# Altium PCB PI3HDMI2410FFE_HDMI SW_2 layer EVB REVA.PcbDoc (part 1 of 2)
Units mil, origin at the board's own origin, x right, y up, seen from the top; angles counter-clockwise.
Board outline 4919 x 3441 mil, 2 copper layers (Top Layer, Bottom Layer); 75 components, 82 nets, 1371 pads, 135 vias.
Unrouted connection lines stored in the file: 1.
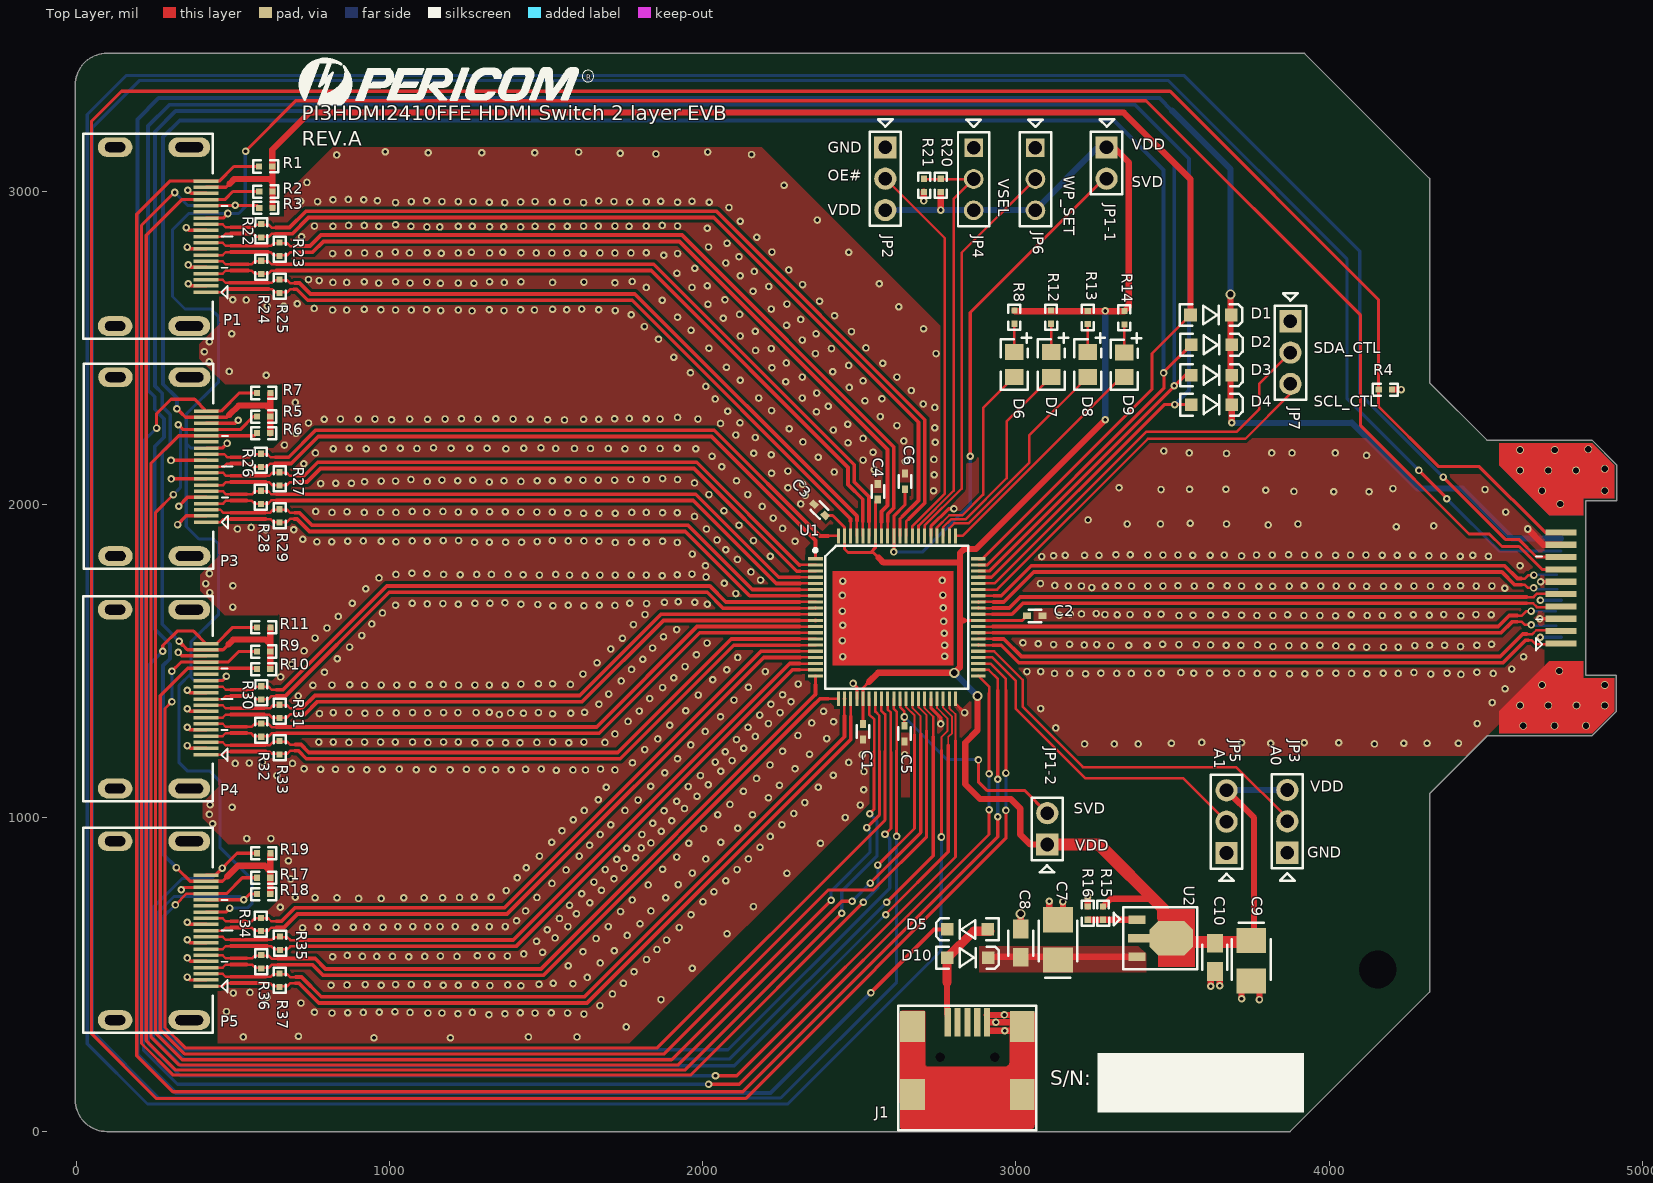
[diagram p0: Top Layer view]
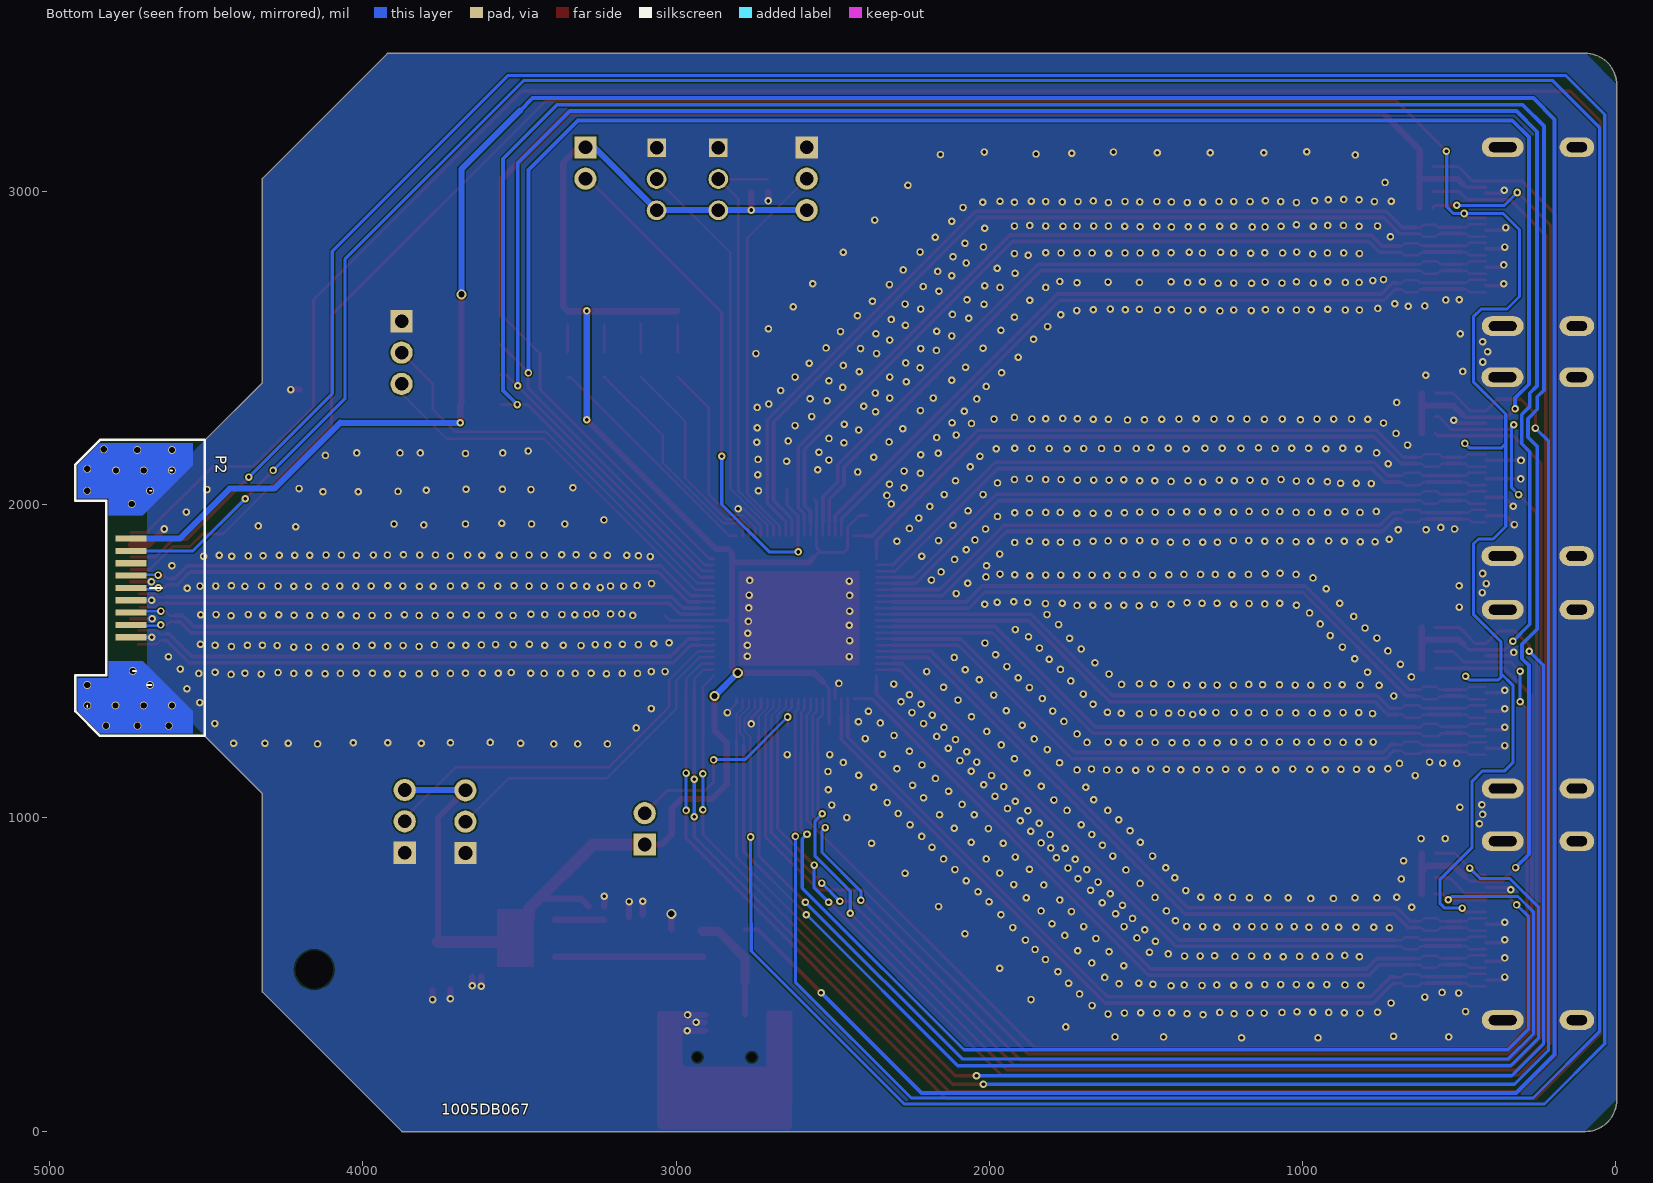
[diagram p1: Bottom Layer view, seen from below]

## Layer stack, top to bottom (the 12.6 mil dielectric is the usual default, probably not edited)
Top Layer: signal copper 1.4
Dielectric: core 12.6, FR-4, Dk 4.8
Bottom Layer: signal copper 1.4

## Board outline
-2,99 ccw(c98,99) 98,-1 3875,-1 4320,444 4320,1077 4505,1262 4838,1262 4916,1340 4916,1456 4819,1456 4819,2012 4917,2012 4917,2127 4838,2206 4503,2206 4320,2389 4320,3041 3921,3440 98,3440 ccw(c97.5,3340.5) -2,3340

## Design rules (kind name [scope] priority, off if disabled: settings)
Clearance [All] p1: gap=5
ComponentClearance [All] p1: gap=0 collisioncheckmode=3 verticalgap=0
DiffPairsRouting [All] p1: maxlimit=10 minlimit=8 mostfreqgap=10 toplayer_maxgap=8 toplayer_prefgap=8 bottomlayer_maxgap=8 bottomlayer_prefgap=8 maxuncoupledlength=500
HoleSize [All] p1: absolutevalues=TRUE maxlimit=500 minlimit=1 maxpercent=80.000 minpercent=20.000
PlaneConnect [All] p1: planeconnectstyle=Direct reliefexpansion=20 reliefentries=4 reliefconductorwidth=10 reliefairgap=10
PolygonConnect [All] p1: connectstyle=Direct reliefconductorwidth=10 reliefentries=4 polygonreliefangle="90 Angle"
RoomDefinition "PI3HDMI2410 demo board" [InComponentClass('PI3HDMI2410 demo board')] p1: confinementstyle=ConfineIn formatcopy=TRUE lockcomponents=FALSE outline -1506,-1019 22894,-1019 22894,6811 -1506,6811
RoutingVias [All] p1: holewidth=28 width=50 viastyle="Through Hole" minholewidth=8 minwidth=10 maxholewidth=28 maxwidth=50
SolderMaskExpansion [All] p1: expansion=4
TestPointUsage [All] p1: valid=0 allowmultiple=FALSE
Testpoint [All] p1: side=15 testpointundercomponent=TRUE minsize=40 maxsize=100 preferedsize=60 minholesize=0 maxholesize=40 preferedholesize=32 testpointgrid=1 style=1023 order=0123456789
Width [All] p1: maxlimit=100 minlimit=6 preferedwidth=10
15 further rules are at their usual default settings.

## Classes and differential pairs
differential pair NewDifferentialPair1: +D0+ -D0-
differential pair NewDifferentialPair2: +D0A+ -D0A-
differential pair NewDifferentialPair3: +D0B+ -D0B-
differential pair NewDifferentialPair4: +D0C+ -D0C-
differential pair NewDifferentialPair5: +D0D+ -D0D-
differential pair NewDifferentialPair6: +D1+ -D1-
differential pair NewDifferentialPair7: +D1A+ -D1A-
differential pair NewDifferentialPair8: +D1B+ -D1B-
differential pair NewDifferentialPair9: +D1C+ -D1C-
differential pair NewDifferentialPair10: +D1D+ -D1D-
differential pair NewDifferentialPair11: +D2+ -D2-
differential pair NewDifferentialPair12: +D2A+ -D2A-
differential pair NewDifferentialPair13: +D2B+ -D2B-
differential pair NewDifferentialPair14: +D2C+ -D2C-
differential pair NewDifferentialPair15: +D2D+ -D2D-
differential pair NewDifferentialPair16: +D3+ -D3-
differential pair NewDifferentialPair17: +D3A+ -D3A-
differential pair NewDifferentialPair18: +D3B+ -D3B-
differential pair NewDifferentialPair19: +D3C+ -D3C-
differential pair NewDifferentialPair20: +D3D+ -D3D-

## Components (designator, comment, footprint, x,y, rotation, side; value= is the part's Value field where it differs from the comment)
C1 "10n" CC_0402 2512,1275 r270 top
C2 "10n" CC_0402 3060,1645 r0 top
C3 "10n" CC_0402 2373,1983 r135 top
C4 "10n" CC_0402 2559,2041 r90 top
C5 "10n" CC_0402 2644,1269 r270 top
C6 "10n" CC_0402 2646,2074 r90 top
C7 "22u" CT_3528 3134,611 r90 top
C8 "1u" CC_0805 3015,600 r270 top
C9 "22u" CT_3528 3751,544 r270 top
C10 "1u" CC_0805 3635,555 r90 top
D1 "B0520LW" D_SOD_123 3622,2605 r0 top
D2 "B0520LW" D_SOD_123 3624,2510 r0 top
D3 "B0520LW" D_SOD_123 3624,2413 r0 top
D4 "B0520LW" D_SOD_123 3624,2319 r0 top
D5 "B0520LW" D_SOD_123 2845,644 r180 top
D6 "LED" LED_0805 2994,2447 r270 top
D7 "LED" LED_0805 3112,2447 r270 top
D8 "LED" LED_0805 3229,2447 r270 top
D9 "LED" LED_0805 3345,2446 r270 top
D10 "B0520LW" D_SOD_123 2846,554 r0 top
J1 "Mini USB 2.0 Type B Female" CON_USB2.0_MiniB_SMT 2845,29 r90 top
JP1-1 "CON 2" "2x1 Pin Header" 3289,3140 r270 top
JP1-2 "CON 2" "2x1 Pin Header" 3100,915 r90 top
JP2 "CON 3" "3x1 Pin Header" 2583,3140 r270 top
JP3 "CON 3" "3x1 Pin Header" 3866,889 r90 top
JP4 "CON 3" PLUG-3PIN@3PIN-100 2865,3139 r270 top
JP5 "CON 3" "3x1 Pin Header" 3672,888 r90 top
JP6 "CON 3" PLUG-3PIN@3PIN-100 3062,3139 r270 top
JP7 "CON 3" "3x1 Pin Header" 3876,2585 r270 top
P1 "HDMI-R" CON_HDMI_Recept 404,2678 r270 top
P2 "HDMI-T" CON_HDMI_Plug 4779,1734.05 r180 bottom
P3 "HDMI-R" CON_HDMI_Recept 405,1944 r270 top
P4 "HDMI-R" CON_HDMI_Recept 404,1202 r270 top
P5 "HDMI-R" CON_HDMI_Recept 404,463 r270 top
R1 "1K" R_0402 605,3079 r0 top
R2 "47K" R_0402 606,2999 r180 top
R3 "47K" R_0402 606,2947 r180 top
R4 "100k" R_0402 4179,2367 r180 top
R5 "47K" R_0402 599.05,2280.97 r180 top
R6 "47K" R_0402 599.05,2227.97 r180 top
R7 "1K" R_0402 599.05,2355.97 r0 top
R8 "1K" R_0402 2995,2598 r90 top
R9 "47K" R_0402 599.05,1530.97 r180 top
R10 "47K" R_0402 599.05,1474.97 r180 top
R11 "1K" R_0402 599.05,1607.97 r0 top
R12 "1K" R_0402 3112,2598 r90 top
R13 "1K" R_0402 3229,2597 r90 top
R14 "1K" R_0402 3346,2596 r90 top
R15 "NP" R_0402 3278,696 r90 top
R16 "0" R_0402 3229,696 r90 top
R17 "47K" R_0402 599.05,808.97 r180 top
R18 "47K" R_0402 599.05,756.97 r180 top
R19 "1K" R_0402 599.05,886.97 r0 top
R20 "1K" R_0402 2760,3019 r270 top
R21 "1K" R_0402 2707,3019 r270 top
R22 "620" R_0402 591,2874 r270 top
R23 "620" R_0402 650,2815 r270 top
R24 "620" R_0402 591,2757 r270 top
R25 "620" R_0402 650,2697 r270 top
R26 "620" R_0402 590,2141 r270 top
R27 "620" R_0402 650,2082 r270 top
R28 "620" R_0402 590,2023 r270 top
R29 "620" R_0402 650,1964 r270 top
R30 "620" R_0402 591,1399 r270 top
R31 "620" R_0402 650,1340 r270 top
R32 "620" R_0402 591,1280 r270 top
R33 "620" R_0402 650,1224 r270 top
R34 "620" R_0402 590,660 r270 top
R35 "620" R_0402 651,600 r270 top
R36 "620" R_0402 591,541 r270 top
R37 "620" R_0402 650,482 r270 top
U1 "PI3HDMI2410" LQFP80 2620,1640 r0 top
U2 "CJ1117-3.3" Pow_SOT_89 3441,616 r270 top
? "" "Lable Hole" 4155,516 r0 top
? "" PSC_LOG 820,3379 r0 top

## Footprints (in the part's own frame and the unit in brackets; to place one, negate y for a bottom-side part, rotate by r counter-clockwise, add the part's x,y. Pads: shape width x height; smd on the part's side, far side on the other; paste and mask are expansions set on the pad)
"2x1 Pin Header" [mm] "Pin Header 2x1 Pitch 2.54mm"
  rect 1.8x1.8 hole 1.1: 1(0,0)
  round 1.8 hole 1.1: 2(2.54,0)
  silkscreen extent -2.27,-1.27 3.81,1.27
"3x1 Pin Header" [mm] "Pin Header 3x1 Pitch 2.54mm"
  rect 1.8x1.8 / inner round 1.8 / far side rect 1.8x1.8 hole 1.1: 1(0,0)
  round 1.8 hole 1.1: 2(2.54,0) 3(5.08,0)
  silkscreen extent -2.27,-1.27 6.35,1.27
CC_0402 [mil]
  rect 25x20 smd: 1(-25,0) 2(25,0)
  silkscreen extent -20,-20 20,20
CC_0805 [mil]
  rect 60x50 smd: 1(-45,0) 2(45,0)
  silkscreen extent -40,-40 40,40
CON_HDMI_Plug [mm]
  rect 2.5x0.5 smd far side: 1(1,-4.5) 3(1,-3.5) 5(1,-2.5) 7(1,-1.5) 9(1,-0.5) 11(1,0.5) 13(1,1.5) 15(1,2.5) 17(1,3.5) 19(1,4.5)
  rect 2.5x0.5 smd: 2(1,-4) 4(1,-3) 6(1,-2) 8(1,-1) 10(1,0) 12(1,1) 14(1,2) 16(1,3) 18(1,4)
  round 0.635 hole 0.508: 20(-2.54,-9.525) 20(-2.54,-7.874) 20(-2.54,7.874) 20(-2.54,9.652) 20(-1.21,11.24) 20(-1.016,-11.176) 20(-0.254,-9.525) 20(-0.22,9.525) 20(1.067,6.807) 20(1.143,-6.731) 20(1.51,11.176) 20(1.524,-11.176) 20(2.032,-9.525) 20(2.032,9.525) 20(2.54,-7.874) 20(2.54,7.874) 20(4.064,-11.176) 20(4.318,-9.525) 20(4.318,9.525) 20(4.32,11.18)
  Top Layer region: -0.813,-5.944 1.968,-5.944 6.013,-9.989 6.013,-11.779 -1.517,-11.779 -1.524,-11.786 -3.302,-10.008 -3.302,-7.315 -0.813,-7.315
  Top Layer region: -0.813,5.893 1.968,5.893 6.013,9.938 6.013,11.728 -1.517,11.728 -1.524,11.735 -3.302,9.957 -3.302,7.264 -0.813,7.264
  Bottom Layer region: -0.813,-5.944 1.968,-5.944 6.013,-9.989 6.013,-11.779 -1.517,-11.779 -1.524,-11.786 -3.302,-10.008 -3.302,-7.315 -0.813,-7.315
  Bottom Layer region: -0.813,5.893 1.968,5.893 6.013,9.938 6.013,11.728 -1.517,11.728 -1.524,11.735 -3.302,9.957 -3.302,7.264 -0.813,7.264
  silkscreen extent -3.5,-12 7,12
CON_HDMI_Recept [mm]
  rect 0.28x2 smd: 1(0,0.281) 2(-0.5,0.281) 3(-1,0.281) 4(-1.5,0.281) 5(-2,0.281) 6(-2.5,0.281) 7(-3,0.281) 8(-3.5,0.281) 9(-4,0.281) 10(-4.5,0.281) 11(-5,0.281) 12(-5.5,0.281) 13(-6,0.281) 14(-6.5,0.281) 15(-7,0.281) 16(-7.5,0.281) 17(-8,0.281) 18(-8.5,0.281) 19(-9,0.281)
  oval 1.6x3.4 hole 0.8 slot 2.25 at 90 deg: 20(-11.75,-1.08) 21(2.75,-1.08)
  oval 1.6x2.8 hole 0.8 slot 1.65 at 90 deg: 22(-11.75,-7.09) 23(2.75,-7.09)
  silkscreen extent -12.82,-9.68 3.78,2.41
CON_USB2.0_MiniB_SMT [mm]
  rect 2.3x0.5 smd: 1(8.1,1.6) 2(8.1,0.8) 3(8.1,0) 4(8.1,-0.8) 5(8.1,-1.6)
  rect 2.5x2 smd: 5(2.25,4.45) 5(2.25,-4.45) 5(7.75,-4.45) 5(7.75,4.45)
  round 0 hole 0.762 unplated: 10(5.25,-2.2) 11(5.25,2.2)
  Top Layer region: 1.58,5.45 -0.35,5.45 -0.438,5.432 -0.513,5.383 -0.562,5.308 -0.58,5.22 -0.58,5.22 -0.58,-5.09 -0.553,-5.224 -0.477,-5.337 -0.364,-5.413 -0.23,-5.44 -0.23,-5.44 8.81,-5.44 8.875,-5.427 8.93,-5.39 8.967,-5.335 8.98,-5.27 8.98,-5.27 8.98,-3.59 8.968,-3.529 8.933,-3.477 8.881,-3.442 8.82,-3.43 8.82,-3.43 4.93,-3.43 4.758,-3.396 4.612,-3.298 4.514,-3.152 4.48,-2.98 4.48,-2.98 4.48,3.17 4.5,3.269 4.556,3.354 4.641,3.41 4.74,3.43 4.74,3.43 8.93,3.43 8.964,3.437 8.994,3.456 9.013,3.486 9.02,3.52 9.02,3.52 9.02,5.26 9.004,5.34 8.958,5.408 8.89,5.454 8.81,5.47 8.81,5.47 1.6,5.47 1.592,5.468 1.586,5.464 1.582,5.458 1.58,5.45
  silkscreen extent -0.65,-5.59 9.45,5.6
CT_3528 [mil]
  rect 80x95 smd: 1(-64,0) 2(64,0)
  silkscreen extent -121,-62 60,62
D_SOD_123 [mil]
  rect 40x40 smd: 1(-65,0) 2(65,0)
  silkscreen extent -100,-35 100,35
"Lable Hole" [mil]
  round 0 hole 120 unplated: ""(0,0)
LED_0805 [mm] "Chip Resistor; Body 2 x 1.3 mm (LxW typ)"
  rect 1.3x1.5 smd: 1(-1,0) 2(1,0)
  silkscreen extent -2.54,-1.09 2.03,1.4
LQFP80 [mm]
  rect 1.2x0.25 smd: 1(-6.6,4.75) 2(-6.6,4.25) 3(-6.6,3.75) 4(-6.6,3.25) 5(-6.6,2.75) 6(-6.6,2.25) 7(-6.6,1.75) 8(-6.6,1.25) 9(-6.6,0.75) 10(-6.6,0.25) 11(-6.6,-0.25) 12(-6.6,-0.75) 13(-6.6,-1.25) 14(-6.6,-1.75) 15(-6.6,-2.25) 16(-6.6,-2.75) 17(-6.6,-3.25) 18(-6.6,-3.75) 19(-6.6,-4.25) 20(-6.6,-4.75) 41(6.6,-4.75) 42(6.6,-4.25) 43(6.6,-3.75) 44(6.6,-3.25) 45(6.6,-2.75) 46(6.6,-2.25) 47(6.6,-1.75) 48(6.6,-1.25) 49(6.6,-0.75) 50(6.6,-0.25) 51(6.6,0.25) 52(6.6,0.75) 53(6.6,1.25) 54(6.6,1.75) 55(6.6,2.25) 56(6.6,2.75) 57(6.6,3.25) 58(6.6,3.75) 59(6.6,4.25) 60(6.6,4.75)
  rect 0.25x1.2 smd: 21(-4.75,-6.6) 22(-4.25,-6.6) 23(-3.75,-6.6) 24(-3.25,-6.6) 25(-2.75,-6.6) 26(-2.25,-6.6) 27(-1.75,-6.6) 28(-1.25,-6.6) 29(-0.75,-6.6) 30(-0.25,-6.6) 31(0.26,-6.6) 32(0.75,-6.6) 33(1.25,-6.6) 34(1.76,-6.6) 35(2.25,-6.6) 36(2.75,-6.6) 37(3.25,-6.6) 38(3.75,-6.6) 39(4.25,-6.6) 40(4.75,-6.6) 61(4.75,6.6) 62(4.25,6.6) 63(3.75,6.6) 64(3.24,6.6) 65(2.75,6.6) 66(2.25,6.6) 67(1.75,6.6) 68(1.25,6.6) 69(0.75,6.6) 70(0.25,6.6) 71(-0.25,6.6) 72(-0.75,6.6) 73(-1.25,6.6) 74(-1.75,6.6) 75(-2.26,6.6) 76(-2.75,6.6) 77(-3.25,6.6) 78(-3.75,6.6) 79(-4.25,6.6) 80(-4.75,6.6)
  silkscreen extent -6.73,-5.79 5.79,5.79
PLUG-3PIN@3PIN-100 [mm] "Pin Header 3x1 Pitch 2.54mm"
  rect 1.5x1.5 hole 1.1: 1(0,0)
  round 1.6 hole 1.1: 2(2.54,0) 3(5.08,0)
  silkscreen extent -2.27,-1.27 6.35,1.27
Pow_SOT_89 [mm] "SOT-89; Body 4.6 x 4.25 mm, inc. leads (LxW max)"
  rect 0.7x1.35 smd: 1(-1.5,-1.388) 3(1.5,-1.388)
  oct 2.8x3.5 smd: 2(0,1.388)
  rect 0.7x1.9 smd: 2(0,-1.163)
  Top Layer region: -2.346,0.336 -2.346,3.302 2.322,3.302 2.323,3.303 2.323,0.338 2.325,0.336
  silkscreen extent -2.5,-3.28 2.5,3.49
PSC_LOG [mil]
  silkscreen extent -107,-103 833,45
R_0402 [mm]
  rect 0.5x0.5 smd: 1(-0.532,-0.001) 2(0.54,-0.001)
  silkscreen extent -1.02,-0.49 1.02,0.49

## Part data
C1 C2 C3 C4 C5 C6 C8 C10: library part "CAP NP"
C7 C9: library part CAP
D1 D2 D3 D4 D5 D10: library part "Diode B0520LW"
J1: library part "USB 2_0.0 Mini B Female"
P1 P2 P3 P4 P5: library part "CON HDMI19_A pin mame"
R1 R2 R3 R4 R5 R6 R7 R8 R9 R10 R11 R12 R13 R14 R15 R16 R17 R18 R19 R20 R21: library part R
R22 R23 R24 R25 R26 R27 R28 R29 R30 R31 R32 R33 R34 R35 R36 R37: library part R_0402
U2: library part Pow_LDO_3.3V

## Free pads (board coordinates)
  round 24 hole 12: 4(61020,24994) 6(1717,2967) 7(1720,2889) 9(1720,2708) 10(1721,2619) 11(1620,2964) 12(1620,2889) 13(1619,2802) 14(1621,2710) 15(1614,2624) 16(1520,2966) 17(1519,2887) 18(1519,2803) 19(1521,2709) 20(1521,2623) 21(1419,2966) 22(1419,2886) 23(1420,2804) 24(1420,2711) 25(1419,2622) 26(1319,2965) 27(1320,2887) 28(1320,2803) 29(1320,2711) 30(1319,2622) 31(1220,2621) 32(1220,2707) 33(1220,2803) 34(1220,2888) 35(1220,2967) 36(1119,2970) 37(1120,2886) 38(1121,2804) 39(1120,2710) 40(1119,2622) 41(1020,2621) 42(1020,2711) 43(1019,2806) 44(1020,2893) 45(920,2891) 46(921,2803) 47(920,2711) 48(920,2623) 49(543,2653) 50(820,2709) 51(819,2801) 52(820,2888) 53(1020,2964) 54(918,2973) 55(820,2973) 56(720,2855) 57(742,2718) 58(500,2654) 59(1820,2967) 60(1820,2889) 61(1820,2804) 62(1820,2693) 63(1814,2568) 64(1920,2965) 65(1920,2889) 66(1920,2801) 67(1920,2598) 68(2040,2337) 69(2021,2965) 70(2015,2882) 71(2015,2698) 72(2020,2499) 73(2080,2298) 74(2120,2904) 75(2116,2791) 76(2118,2607) 77(2120,2397) 78(2119,2261) 79(2221,2806) 80(2211,2696) 81(2220,2300) 82(2030,2154) 83(2061,2121) 84(2320,2200) 85(2318,2407) 86(2313,2591) 87(2319,2702) 88(2421,2603) 89(2411,2498) 90(2401,2314) 91(2420,2104) 92(2521,2500) 93(2512,2395) 94(2512,2211) 95(2620,2252) 96(2620,2407) 97(2737,2044) 98(2738,2144) 99(2741,2245) 100(2704,2321) 101(2318,2340) 102(2417,2238) 103(2512,2142) 104(2019,2822) 105(2120,2730) 106(2219,2624) 107(2318,2525) 108(2415,2424) 109(2518,2331) 110(1918,2738) 111(2017,2639) 112(2120,2538) 113(2219,2498) 114(2221,2437) 115(1920,2278) 116(1820,2274) 117(1719,2274) 118(1620,2272) 119(1450,2272) 120(1395,2273) 121(1283,2273) 122(844,2273) 123(792,2272) 124(742,2260) 125(665,2190) 126(702,2227) 127(3258,1553) 128(3242,1735) 129(3256,1652) 132(1420,2074) 133(1319,2072) 134(1218,2076) 135(1121,2074) 136(879,2068) 137(829,2068) 138(781,2067) 139(817,1975) 140(920,1975) 141(1021,1975) 142(1707,978) 144(727,2130) 145(764,2165) 146(981,2180) 147(1312,2180) 149(1429,2180) 150(2012,1922) 151(1351,1330) 152(1688,1241) 153(1804,904) 154(821,2178) 155(872,2180) 156(926,2178) 157(1035,2180) 158(1088,2179) 159(1141,2181) 160(1197,2180) 161(1372,2178) 162(1257,2180) 163(1484,2181) 164(1531,2179) 165(1591,2179) 166(1642,2179) 167(1699,2179) 168(1752,2178) 169(1809,2179) 170(1864,2179) 171(1978,2178) 172(1919,2180) 173(901,2273) 174(954,2273) 175(1340,2274) 176(1007,2271) 177(1065,2273) 178(1122,2272) 179(1178,2273) 180(1230,2274) 181(1505,2271) 182(1559,2270) 183(1668,2272) 184(1766,2275) 185(1864,2273) 186(1985,2273) 187(2057,2259) 188(869,2974) 189(962,2970) 190(1070,2967) 191(1168,2967) 192(1267,2967) 193(1368,2964) 194(1465,2967) 195(1567,2967) 196(1668,2969) 197(1767,2966) 198(1866,2968) 199(1966,2968) 200(1871,2891) 201(1765,2888) 202(1667,2889) 203(1568,2888) 204(1465,2888) 205(1365,2887) 206(1265,2888) 207(1161,2886) 208(1069,2888) 209(1064,2803) 210(1166,2802) 211(1262,2805) 212(1362,2805) 213(1469,2803) 214(1567,2803) 215(1672,2803) 216(1720,2803) 217(1771,2803) 218(1775,2712) 219(1772,2606) 220(1668,2622) 221(1566,2622) 222(1463,2621) 223(1366,2619) 224(1367,2709) 225(1270,2706) 226(1163,2706) 227(1066,2707) 228(966,2707) 229(968,2800) 230(966,2888) 231(870,2891) 232(869,2803) 233(864,2709) 234(864,2621) 235(819,2621) 236(760,2626) 237(706,2641) 238(771,2967) 239(717,2968) 240(761,2889) 241(776,2715) 242(1876,2796) 243(1871,2652) 244(1859,2528) 245(1975,2754) 246(1966,2693) 247(1963,2556) 248(2071,2654) 249(2066,2595) 250(2078,2834) 251(2074,2771) 252(2084,2948) 253(2173,2853) 254(2275,2749) 255(2373,2649) 256(2475,2552) 257(2575,2451) 258(2269,2640) 259(2268,2572) 260(2165,2744) 261(2161,2681) 262(2362,2545) 263(2360,2482) 264(2267,2452) 265(2265,2392) 266(2168,2553) 267(2169,2492) 268(2364,2356) 269(2363,2296) 270(2276,2242) 271(2179,2340) 272(2076,2438) 273(2463,2256) 274(2464,2197) 275(2369,2151) 276(2168,2214) 277(2219,2159) 278(2272,2107) 279(2319,2065) 280(2106,2222) 281(2163,2164) 282(2220,2100) 283(2272,2054) 284(2313,2002) 285(2466,2444) 286(2468,2374) 287(2572,2338) 288(2567,2281) 289(2666,2364) 290(2642,2203) 291(2742,2199) 292(2739,2095) 293(2544,2167) 294(973,2622) 295(1070,2621) 296(1164,2619) 297(1264,2618) 298(1908,2470) 299(1961,2421) 300(2010,2377) 301(921,2073) 302(974,2075) 303(1020,2075) 304(1069,2080) 305(1168,2078) 306(1266,2078) 307(1366,2076) 308(1472,2076) 309(1520,2076) 310(1571,2079) 311(1618,2078) 312(1667,2078) 313(1719,2078) 314(1771,2080) 315(1820,2080) 316(1872,2083) 317(1920,2080) 318(1974,2069) 319(2020,2032) 320(2068,1980) 321(2116,1934) 322(2162,1885) 323(2216,1835) 324(765,1978) 325(865,1977) 326(972,1975) 327(1073,1978) 328(1119,1976) 329(1171,1978) 330(1171,1978) 331(1220,1976) 332(1271,1977) 333(1320,1977) 334(1370,1977) 335(1420,1976) 336(1471,1976) 337(1520,1976) 338(1569,1974) 339(1620,1972) 340(1669,1972) 341(1721,1972) 342(1774,1975) 343(1820,1975) 344(1872,1974) 345(1919,1974) 346(1974,1962) 347(2046,1887) 348(2074,1856) 349(2111,1825) 350(2154,1785) 351(2185,1759) 352(515,1922) 353(559,1927) 354(606,1920) 355(695,1920) 356(724,1889) 357(769,1881) 358(867,1883) 359(917,1884) 360(974,1883) 361(1021,1881) 362(1073,1884) 363(1121,1883) 364(1172,1885) 365(1221,1885) 366(1272,1880) 367(1319,1880) 368(1371,1880) 369(1422,1880) 370(1472,1882) 371(1520,1885) 372(1571,1884) 373(1621,1884) 374(1669,1883) 375(1721,1879) 376(1773,1880) 377(1820,1880) 378(1872,1883) 379(1919,1879) 380(1967,1842) 381(2009,1805) 382(2069,1749) 383(2106,1716) 384(1021,1777) 385(1120,1779) 386(1072,1781) 387(1173,1777) 388(1226,1776) 389(1279,1777) 390(1326,1777) 391(1379,1777) 392(1427,1776) 393(1479,1775) 394(1531,1777) 395(1575,1775) 396(1625,1774) 397(1672,1775) 398(1721,1775) 399(1772,1775) 400(1820,1775) 401(1871,1773) 402(1919,1776) 403(1966,1778) 404(2011,1769) 405(1020,1679) 406(967,1766) 407(925,1731) 408(882,1685) 409(837,1643) 410(801,1606) 411(763,1574) 412(728,1533) 413(688,1490) 414(653,1450) 415(709,1389) 416(756,1423) 417(793,1465) 418(834,1508) 419(873,1545) 420(912,1582) 421(944,1619) 422(978,1654) 423(1073,1685) 424(1121,1683) 425(1171,1684) 426(1220,1682) 427(1273,1685) 428(1321,1685) 429(1369,1687) 430(1420,1682) 431(1474,1681) 432(1522,1677) 433(1571,1679) 434(1621,1677) 435(1670,1679) 436(1720,1678) 437(1767,1685) 438(1821,1684) 439(1878,1688) 440(1922,1690) 441(1975,1688) 442(2015,1682) 443(817,1424) 444(874,1425) 445(921,1424) 446(974,1424) 447(1024,1424) 448(1074,1425) 449(1128,1425) 450(1172,1426) 451(1221,1424) 452(1273,1424) 453(1319,1424) 454(1370,1424) 455(1420,1427) 456(1476,1428) 457(1521,1428) 458(1578,1426) 459(1618,1459) 460(1663,1495) 461(1707,1539) 462(1744,1573) 463(1779,1617) 464(1816,1649) 465(777,1333) 466(821,1336) 467(871,1336) 468(922,1334) 469(969,1335) 470(1022,1335) 471(1074,1336) 472(1122,1335) 473(1173,1336) 474(1219,1336) 475(1277,1336) 476(1319,1337) 477(1387,1335) 478(1428,1334) 479(1476,1336) 480(1521,1332) 481(1579,1334) 482(1623,1337) 483(1669,1363) 484(1700,1395) 485(1740,1437) 486(1773,1474) 487(1809,1506) 488(1840,1542) 489(1875,1578) 490(1917,1601) 491(508,1174) 492(553,1175) 493(595,1178) 494(691,1174) 495(728,1157) 496(781,1155) 497(828,1155) 498(878,1155) 499(928,1154) 500(977,1155) 501(545,934) 501(622,934) 501(1032,1156) 501(1086,1154) 501(1139,1155) 501(1194,1154) 501(1885,610) 501(1925,650) 501(2087,1043) 501(2146,869) 501(2159,1010) 501(2183,906) 501(2326,1049) 501(2503,1041) 501(2514,1090) 501(2515,1148) 516(1389,1154) 550(1632,491) 566(1437,841) 571(641,1135) 577(678,863) 592(685,805) 593(652,715) 594(700,747) 595(763,745) 596(833,745) 597(902,743) 598(974,743) 599(1046,745) 600(1111,745) 601(1170,745) 602(1224,746) 603(1271,747) 604(1325,747) 605(1373,768) 606(1408,809) 607(1479,878) 608(1518,922) 610(1297,1154) 611(1246,1155) 612(1435,1155) 613(1339,1154) 614(1485,1156) 615(1533,1152) 616(1586,1153) 617(1626,1153) 618(1674,1156) 619(1720,1153) 620(1692,1098) 621(1667,1058) 622(1622,1024) 623(1587,994) 624(1551,959) 629(1776,1176) 630(1815,1218) 631(1857,1252) 632(1895,1296) 633(1946,1342) 634(1986,1392) 635(2032,1441) 636(2077,1473) 637(2112,1512) 638(723,649) 639(773,651) 640(830,651) 641(885,651) 642(928,652) 643(980,651) 644(1027,653) 645(1075,653) 646(1122,653) 647(1162,653) 648(1210,653) 649(1274,651) 650(1319,653) 651(1370,653) 652(1406,672) 653(1435,703) 654(1471,746) 655(1519,791) 656(1564,834) 657(1606,878) 658(1639,913) 659(1673,947) 660(1752,1024) 661(1794,1057) 662(1834,1101) 663(1879,1144) 664(1920,1189) 665(1962,1233) 666(2008,1276) 667(2057,1323) 668(2100,1376) 669(2146,1417) 670(2200,1467) 671(2305,1427) 672(2255,1393) 673(2282,1371) 674(2218,1363) 675(2182,1328) 676(2145,1289) 677(2108,1250) 678(2072,1211) 679(2040,1178) 680(1993,1135) 681(2247,1336) 682(2210,1301) 683(2168,1260) 684(2131,1222) 685(2094,1183) 686(2058,1149) 687(2018,1106) 688(1954,1100) 689(1982,1069) 690(1917,1053) 691(1942,1030) 692(1877,1023) 693(1901,991) 694(1841,983) 695(1868,957) 696(1806,947) 697(1835,920) 698(1758,903) 699(1786,873) 700(1726,868) 701(1749,840) 702(1689,835) 703(1653,795) 704(1614,758) 705(1575,721) 706(1543,679) 707(1504,643) 708(1470,606) 709(1429,566) 710(1717,806) 711(1677,769) 712(1640,729) 713(1597,694) 714(1570,653) 715(1529,617) 716(1489,571) 717(1377,559) 718(1327,559) 719(1281,560) 720(1216,558) 721(1163,559) 722(1113,558) 723(1062,557) 724(1010,558) 725(960,558) 726(914,558) 727(866,561) 728(819,557) 729(814,466) 730(865,467) 731(923,468) 732(974,466) 733(1020,468) 734(1070,468) 735(1121,468) 736(1172,466) 737(1220,466) 738(1274,467) 739(1321,465) 740(1378,467) 741(1420,464) 742(1478,469) 743(1523,472) 744(1571,528) 745(1618,573) 746(1660,615) 747(1699,653) 748(1738,701) 749(1775,738) 750(1826,786) 751(1872,836) 752(1917,875) 753(1956,919) 754(1586,471) 755(1673,537) 756(1718,576) 757(1759,625) 758(1800,662) 759(1835,703) 760(1882,745) 761(1922,787) 762(1967,824) 763(2003,966) 764(2048,1010) 765(2130,1085) 766(2172,1126) 767(2215,1169) 768(2255,1213) 769(2304,1263) 770(2010,869) 771(2058,922) 772(2112,967) 773(2210,1064) 774(2245,1104) 775(2295,1157) 776(2348,1303) 777(2386,1340) 778(2418,1307) 779(2396,1253) 780(2341,1203) 781(2466,1177) 782(2417,1136) 783(2369,1098) 784(2291,1014) 785(2253,978) 786(2216,941) 787(2110,835) 788(2074,799) 789(2036,764) 790(2001,732) 791(1963,691) 792(1854,580) 793(1821,548) 794(1781,509) 795(1747,472) 796(1712,438) 797(1672,401) 798(1621,374) 799(1569,377) 800(1517,378) 801(1465,377) 802(1418,378) 803(1369,375) 804(1318,372) 805(1265,379) 806(1219,375) 807(1168,377) 808(1123,377) 809(1066,379) 810(1018,381) 811(968,380) 812(917,379) 813(867,378) 814(817,377) 815(761,380) 816(718,409) 817(610,428) 818(555,443) 819(502,441) 820(4609,1805) 823(4508,1835) 824(4458,1838) 825(4418,1835) 826(4365,1836) 827(4318,1837) 828(4266,1838) 829(4217,1838) 830(4169,1838) 831(4117,1839) 832(4068,1839) 833(4020,1838) 834(3966,1839) 835(3921,1839) 836(3870,1840) 837(3818,1839) 838(3768,1839) 839(3720,1836) 840(3665,1839) 841(3620,1838) 842(3564,1838) 843(3517,1839) 844(3469,1839) 845(3421,1839) 846(3365,1840) 847(3319,1840) 848(3319,1840) 849(3265,1838) 850(3219,1838) 851(3157,1838) 852(3120,1837) 853(3082,1834) 854(3078,1748) 856(3124,1742) 857(3167,1740) 858(3209,1740) 859(3285,1739) 860(3326,1741) 861(3369,1740) 862(3421,1740) 863(3469,1740) 864(3517,1741) 865(3569,1740) 866(3621,1741) 867(3674,1741) 868(3720,1740) 869(3775,1739) 870(3819,1739) 871(3872,1740) 872(3920,1741) 873(3973,1740) 874(4022,1740) 875(4073,1740) 876(4119,1739) 877(4173,1739) 878(4220,1739) 879(4270,1740) 880(4323,1740) 881(4376,1739) 882(4419,1741) 883(4469,1740) 884(4519,1740) 885(4560,1733) 886(4517,1648) 887(4468,1649) 888(4420,1645) 889(4365,1649) 890(4319,1647) 891(4268,1648) 892(4219,1647) 893(4169,1646) 894(4121,1646) 895(4070,1648) 896(4020,1645) 897(3970,1646) 898(3919,1646) 899(3867,1648) 900(3820,1646) 901(3769,1646) 902(3720,1647) 903(3669,1648) 904(3621,1647) 905(3565,1647) 906(3520,1646) 907(3463,1650) 908(3419,1649) 909(3364,1649) 910(3323,1648) 911(3284,1649) 912(3209,1651) 913(3173,1651) 914(3022,1559) 915(3071,1556) 916(3120,1553) 917(3171,1554) 918(3218,1552) 919(3303,1550) 920(3360,1551) 921(3419,1551) 922(3468,1554) 923(3520,1553) 924(3576,1553) 925(3621,1552) 926(3671,1551) 927(3718,1551) 928(3771,1552) 929(3820,1547) 930(3871,1550) 931(3920,1549) 932(3970,1551) 933(4021,1549) 934(4072,1546) 935(4119,1545) 936(4173,1545) 937(4220,1545) 938(4273,1550) 939(4320,1551) 940(4368,1551) 941(4419,1547) 942(4471,1551) 943(4518,1554) 944(3035,1467) 945(3079,1467) 946(3123,1461) 947(3172,1461) 948(3222,1460) 949(3271,1462) 950(3322,1461) 951(3368,1461) 952(3421,1461) 953(3464,1462) 954(3526,1464) 955(3567,1462) 956(3618,1462) 957(3672,1462) 958(3720,1461) 959(3770,1461) 960(3820,1460) 961(3873,1460) 962(3922,1460) 963(3969,1462) 964(4021,1462) 965(4071,1461) 966(4120,1460) 967(4172,1462) 968(4220,1461) 969(4270,1464) 970(4324,1459) 971(4376,1462) 972(4420,1458) 973(4471,1465) 974(4523,1461) 975(4582,1475) 976(4620,1514) 977(775,1242) 978(821,1242) 979(871,1241) 980(921,1242) 981(972,1242) 982(1019,1242) 983(1074,1242) 984(1123,1241) 985(1173,1242) 986(1220,1242) 987(1273,1240) 988(1321,1240) 989(1371,1240) 990(1417,1240) 991(1471,1241) 992(1521,1242) 993(1573,1240) 994(1621,1242) 995(1720,1268) 996(1762,1308) 997(1798,1341) 998(1831,1381) 999(1872,1416) 1000(1908,1447) 1001(1944,1483) 1002(1980,1521) 1003(2014,1558) 1006(3230,1951) 1007(3329,2054) 1008(3672,2163) 1009(4119,2157) 1010(4203,2051) 1011(4333,1932) 1012(3881,2165) 1013(3472,2171) 1014(3355,1938) 1015(3463,2048) 1016(3670,2049) 1017(3887,2042) 1018(4127,2041) 1019(4019,2165) 1020(3816,2165) 1021(3553,2165) 1022(4014,2041) 1023(3797,2046) 1024(3554,2049) 1025(3556,1940) 1026(3461,1938) 1027(3672,1938) 1028(3805,1935) 1029(3900,1938) 1030(4497,2048) 1031(4563,1976) 1032(4214,1929) 1033(3079,1349) 1034(3127,1287) 1035(3219,1236) 1036(3314,1236) 1037(3390,1236) 1038(3496,1238) 1039(3593,1241) 1041(3720,1240) 1042(3813,1238) 1043(3920,1240) 1044(4030,1240) 1046(4144,1236) 1047(4238,1238) 1048(4312,1238) 1049(4412,1238) 1050(4472,1301) 1051(4520,1368) 1052(4561,1412) 1053(2108,2076) 1054(2144,2032) 1055(2190,1994) 1056(2225,1957) 1057(2255,1924) 1058(2295,1883) 1059(832,3116) 1060(737,3028) 1062(987,3126) 1063(1124,3123) 1065(1295,3123) 1066(1464,3123) 1069(1604,3125) 1070(1737,3121) 1072(1851,3119) 1074(2016,3125) 1076(2156,3117) 1079(2260,3019) 1082(2366,2908) 1085(2466,2805) 1088(2564,2705) 1090(2626,2631) 1092(2705,2561) 1094(2745,2482) 1097(2741,2310) 1098(534,301) 1099(480,382) 1101(710,303) 1104(951,298) 1107(1195,298) 1110(1444,301) 1112(1599,301) 1115(1756,333) 1117(1867,420) 1119(1967,520) 1121(2078,630) 1123(2162,717) 1125(2269,823) 1127(2376,919) 1129(2455,1001) 1131(700,2326) 1132(607,2413) 1133(489,2425) 1134(663,2633) 1135(610,2634) 1136(497,2545) 1137(816,1881)

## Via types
v1: diameter 24, hole 12, Top Layer to Bottom Layer, tented both sides, 131 vias
v2: diameter 32, hole 20, Top Layer to Bottom Layer, tented both sides, 4 vias

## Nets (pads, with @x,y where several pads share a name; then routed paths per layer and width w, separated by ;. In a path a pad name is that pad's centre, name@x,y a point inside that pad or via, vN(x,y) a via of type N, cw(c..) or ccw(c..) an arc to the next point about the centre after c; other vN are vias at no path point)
+5V: C7.1 C8.2 D10.2 U2.3 | length 472.4
  Top Layer w20: D10.2@2913.94,556.94 U2.3@3386.37,556.94
+5V_A: D1.1 P1.18 R1.2 R2.1 R3.1 U1.60 | length 4979.4
  Top Layer w10: P1.18@415.06,3012.65 478.65,3012.65 490,3024 ; U1.60@2879.84,1827.01 2893.01,1827.01 3434,2368 3434,2482 D1.1@3557,2605
  Top Layer w20: 490,3024 505,3039 618,3039 626.95,3030.05 ; R3.1@626.95,2947.03 626.95,3078.28 R1.2@626.27,3078.97 626.27,3132.27 745,3251 3344,3251 3557,3038 D1.1@3557,2605
+5V_B: D2.1 P3.18 R5.1 R6.1 R7.2 U1.59 | length 6271.7
  Top Layer w10: 339.11,2288.89 349.35,2278.65 481.65,2278.65 489,2286 ; U1.59@2879.84,1807.32 2908.32,1807.32 3472,2371 3472,2423 D2.1@3559,2510
  Top Layer w12: v1(322,2306) 339.11,2288.89
  Top Layer w20: 489,2286 519,2316 608,2316 620,2304 ; R6.1@620,2228 R7.2@620,2355.62
  Bottom Layer w12: v1(322,2306) 322,2340 278,2384 278,3173 331,3226 3313,3226 3471,3068 v1(3471,2420)
+5V_C: D3.1 P4.18 R9.1 R10.1 R11.2 U1.58 | length 7212
  Top Layer w10: 339.83,1552.17 355.35,1536.65 469.65,1536.65 487,1554 ; U1.58@2879.84,1787.64 2914.64,1787.64 3540,2413 D3.1@3559,2413
  Top Layer w12: v1@328.5,1563.5 339.83,1552.17
  Top Layer w20: 487,1554 502,1569 605,1569 620,1554 R10.1@620,1475 620.31,1475.31 R11.2@620.31,1607.94
  Bottom Layer w12: v1(329,1564) 275,1618 275,2168 301,2194 301,2287 275,2313 275,2355 252,2378 252,3190 318,3256 3339,3256 3505,3090 v1(3505,2379)
+5V_D: D4.1 P5.18 R17.1 R18.1 R19.2 U1.57 | length 8054.7
  Top Layer w10: v1@326.5,835.5 364.35,797.65 467.65,797.65 483,813 ; U1.57@2879.84,1767.95 2921.95,1767.95 3473,2319 D4.1@3559,2319
  Top Layer w12: v1(320.46,841.54) v1@326.5,835.5
  Top Layer w20: 483,813 517,847 602,847 620,829 ; R18.1@620,757 R19.2@620,886.62
  Bottom Layer w12: v1(320.46,841.54) 278,884 278,1486 300,1508 300,1554 251,1603 251,2185 281,2215 281,2274 251,2304 251,2344 230,2365 230,3208 298,3276 3380,3276 3552,3104 3552,2364 v1(3507,2319)
+5V_E: D1.2 D2.2 D3.2 D4.2 D5.2 P2.18 | length 11460.7
  Top Layer w13: v1(2537,442) 2739,644 D5.2@2780,644
  Top Layer w20: v2@3685,2670 3685,2323 D4.2@3689,2319 v1(3689,2261)
  Bottom Layer w13: v1(2537,442) 2217,122 319,122 196,245 196,3229 264,3297 3458,3297 3498.23,3256.77 ; v2@3685,2670 v2(3685,2671)
  Bottom Layer w20: 3498.23,3256.77 3685,3070 v2(3685,2671) ; v1@3687,2260 4070,2260 ; 4072,2261 4282,2051 4424,2051 4583.46,1891.54 P2.18@4739.63,1891.54
+5V_USB: D5.1 D10.1 J1.1 | length 351.3
  Top Layer w20: J1.1@2780.01,372.9 2780.01,476
  Top Layer w30: 2780.01,476 2780.01,553.01 2865,638 D5.1@2916,638
A0: JP3.2 U1.45 | length 1267.2
  Top Layer w8: U1.45@2879.84,1531.73 2930.27,1531.73 3021,1441 3021,1355 3213.69,1162.31 3702.69,1162.31 3866,999 JP3.2@3866,989
A1: JP5.2 U1.44 | length 1061.4
  Top Layer w8: U1.44@2879.84,1512.05 2924.95,1512.05 2999,1438 2999,1349 3222,1126 3534,1126 JP5.2@3672,988
CEC: P1.13 P2.13 P3.13 P4.13 P5.13 | length 8748.7
  Top Layer w10: P5.13@415.06,699.22 478.22,699.22 v1(491,712) ; P4.13@415.06,1438.22 468.22,1438.22 v1(480,1452) ; P1.13@415.06,2914.22 470.22,2914.22 v1(485,2929) ; P3.13@416.06,2180.22 467.22,2180.22 v1(482,2195) ; v1(541,3128) 701,3289 3415,3289 4100,2604 4100,2252 4446,1906 4511,1906 4551,1866 4606,1866 4678.89,1793.11 P2.13@4739.63,1793.11
  Bottom Layer w10: 352,2195 367,2180 467,2180 v1(482,2195) ; 367,1461 329,1423 329,1176 355,1150 426,1150 459,1117 459,906 562,803 562,727 547,712 v1(491,712) ; v1(480,1452) 468,1440 376,1440 367,1449 367,1562 455,1650 455,1874 439,1890 392,1890 352,1930 352,2289 455,2392 455,2599 430,2624 348,2624 308,2664 308,2877 360,2929 519,2929 540,2950 540,3128 v1(541,3128)
D0+: P2.10 U1.53 | length 1910.7
  Top Layer w8: U1.53@2880,1689.06 2928,1689.06 ; 4614.42,1743.74 4624,1743.74 4633.69,1734.06 v1(4652,1734.06)
  Top Layer w12: U1.53@2879.84,1689.21 U1.53@2880,1689.21 ; 2928,1689.06 2961.06,1689.06 3057,1785 4550.72,1785 4591.98,1743.74 4614.42,1743.74
  Bottom Layer w8: v1(4652,1734.06) 4656.06,1730 P2.10@4728,1730
D0-: P2.12 U1.54 | length 1906.1
  Top Layer w8: U1.54@2879.84,1708.9 2929.61,1708.9 ; 4612.94,1763.74 4624,1763.74 4635.26,1775 v1(4653,1775)
  Top Layer w12: 2929.61,1709.06 2952.77,1709.06 3048.71,1805 4559,1805 4600.26,1763.74 4612.94,1763.74
  Bottom Layer w8: v1@4654.57,1776 P2.12@4726,1776
D0A+: P1.10 R22.2 U1.70 | length 2965.8
  Top Layer w8: P1.10@415.06,2855.17 468.32,2855.17 478,2864.85 495,2864.85 ; 555,2864.85 565.15,2864.85 575.68,2854.32 614.32,2854.32 624,2864 637,2864 ; U1.70@2629.84,1899.84 2629.84,1954.13 2637.32,1961.61
  Top Layer w12: 495,2864.85 555,2864.85 ; 637,2864 690,2864 742,2916 2035.72,2916 2689,2262.72 2689,2013.28 2637.32,1961.61
D0A-: P1.12 R22.1 U1.69 | length 2998.4
  Top Layer w8: P1.12@415.06,2894.54 468.32,2894.54 478,2884.85 495,2884.85 ; 555,2884.85 566.85,2884.85 575.68,2893.68 614.32,2893.68 624,2884 638,2884 ; U1.69@2649.53,1899.84 2649.53,1945.53 2657.47,1953.47
  Top Layer w12: 495,2884.85 555,2884.85 ; 638,2884 681.72,2884 733.72,2936 2044,2936 2709,2271 2709,2005 2657.47,1953.47
D0B+: P3.10 R26.2 U1.1 | length 2187.6
  Top Layer w8: P3.10@416.06,2121.17 472.17,2121.17 481.85,2130.85 495,2130.85 ; 540,2130.85 555.46,2130.85 565,2121.32 610.32,2121.32 620,2131 635,2131 ; U1.1@2360.16,1827.01 2360.16,1860
  Top Layer w12: 495,2130.85 540,2130.85 ; 635,2131 687,2131 773,2217 2028.72,2217 2360.09,1885.63 ; 2360.16,1860 2360.16,1885.7
D0B-: P3.12 R26.1 U1.80 | length 2204.4
  Top Layer w8: P3.12@416.06,2160.54 473.32,2160.54 483,2150.85 495,2150.85 ; 540,2150.85 553.85,2150.85 563.68,2160.68 611.32,2160.68 621,2151 636,2151 ; 2400,1899.84 U1.80@2432.99,1899.84
  Top Layer w12: 495,2150.85 540,2150.85 ; 636,2151 678.72,2151 764.72,2237 2037,2237 2374.23,1899.77 ; 2360.62,1913.38 2360.76,1913.38 ; 2374.3,1899.84 2400,1899.84
D0C+: P4.10 R30.2 U1.9 | length 2115.1
  Top Layer w8: P4.10@415.06,1379.17 468.32,1379.17 478,1388.85 495,1388.85 ; 545,1388.85 562.15,1388.85 571.68,1379.32 614.32,1379.32 624,1389 640,1389 ; 2310,1669.37 U1.9@2360,1669.37
  Top Layer w12: 495,1388.85 545,1388.85 ; 640,1389 669,1389 1000,1720 2014.72,1720 2065.35,1669.37 2310,1669.37 ; U1.9@2360,1669.53 U1.9@2360.16,1669.53
D0C-: P4.12 R30.1 U1.8 | length 2115.3
  Top Layer w8: P4.12@415.06,1418.54 468.32,1418.54 478,1408.85 495,1408.85 ; 545,1408.85 563.85,1408.85 573.68,1418.68 614.32,1418.68 624,1409 640,1409 ; 2310,1689.37 2321.38,1689.37 2321.54,1689.21 U1.8@2360.16,1689.21
  Top Layer w12: 495,1408.85 545,1408.85 ; 640,1409 660.72,1409 991.72,1740 2023,1740 2073.63,1689.37 2310,1689.37
D0D+: P5.10 R34.2 U1.17 | length 2314.5
  Top Layer w8: P5.10@415.06,640.17 468.32,640.17 478,649.85 495,649.85 ; 540,649.85 560.15,649.85 569.68,640.32 613.32,640.32 623,650 640,650 ; 2310.32,1511.89 2310.16,1512.05 U1.17@2360.16,1512.05
  Top Layer w12: 495,649.85 540,649.85 ; 640,650 664,650 707,693 1376,693 2194.89,1511.89 2310.32,1511.89
D0D-: P5.12 R34.1 U1.16 | length 2314.3
  Top Layer w8: P5.12@415.06,679.54 468.32,679.54 478,669.85 495,669.85 ; 540,669.85 559.85,669.85 569.68,679.68 613.32,679.68 623,670 640,670 ; 2310,1531.89 2321.38,1531.89 2321.54,1531.73 U1.16@2360.16,1531.73
  Top Layer w12: 495,669.85 540,669.85 ; 640,670 655.72,670 698.72,713 1367.72,713 2186.61,1531.89 2310,1531.89
D1+: P2.7 U1.51 | length 1849.4
  Top Layer w8: U1.51@2879.84,1649.84 2925,1649.84 ; 4630,1684.68 4651,1684.68 4662.69,1673 P2.7@4710,1673
  Top Layer w12: 2925,1649.84 2986.84,1649.84 3021.69,1684.68 4630,1684.68
D1-: P2.9 U1.52 | length 1852.7
  Top Layer w8: U1.52@2879.84,1669.53 2880.16,1669.84 2926,1669.84 ; 4630,1704.68 4652,1704.68 4663.31,1716 P2.9@4713,1716
  Top Layer w12: U1.52@2879.84,1669.84 U1.52@2880.16,1669.84 ; 2926,1669.84 2978.56,1669.84 3013.4,1704.68 4630,1704.68
D1A+: P1.7 R23.2 U1.73 | length 2760.9
  Top Layer w8: P1.7@415.06,2796.11 468.32,2796.11 478,2805.8 495,2805.8 ; 613,2805.8 621.2,2805.8 631.68,2795.32 673.32,2795.32 683,2805 695,2805 ; U1.73@2570.79,1899.84 2570.79,1944.68
  Top Layer w12: 495,2805.8 613,2805.8 ; 695,2805 755,2805 790,2840 1925.72,2840 2590,2175.72 2590,1997.28 2570.47,1977.76 2570.47,1944.68
D1A-: P1.9 R23.1 U1.72 | length 2793.4
  Top Layer w8: P1.9@415.06,2835.48 468.32,2835.48 478,2825.8 495,2825.8 ; 612,2825.8 622.8,2825.8 631.68,2834.68 673.32,2834.68 683,2825 695,2825 ; U1.72@2590.47,1899.84 2590.47,1945
  Top Layer w12: 495,2825.8 612,2825.8 ; 695,2825 746.72,2825 781.72,2860 1934,2860 2610,2184 2610,1989 2590.47,1969.47 2590.47,1945
D1B+: P3.7 R27.2 U1.3 | length 2117.9
  Top Layer w8: P3.7@416.06,2062.11 469.32,2062.11 479,2071.8 495,2071.8 ; 605,2071.8 616.2,2071.8 625.68,2062.32 673.32,2062.32 683,2072 695,2072 ; 2311.52,1787.48 2321.38,1787.48 2321.54,1787.64 U1.3@2360.16,1787.64
  Top Layer w12: 495,2071.8 605,2071.8 ; 695,2072 737,2072 780,2115 1972.72,2115 2300.24,1787.48 2311.52,1787.48 2303.24,1787.48
D1B-: P3.9 R27.1 U1.2 | length 2109.7
  Top Layer w8: P3.9@416.06,2101.48 469.32,2101.48 479,2091.8 495,2091.8 ; 605,2091.8 616.8,2091.8 626.68,2101.68 672.32,2101.68 682,2092 695,2092 ; 2308.68,1807.32 U1.2@2360.16,1807.32
  Top Layer w12: 495,2091.8 605,2091.8 ; 695,2092 728.72,2092 771.72,2135 1981,2135 2308.52,1807.48 2308.68,1807.48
